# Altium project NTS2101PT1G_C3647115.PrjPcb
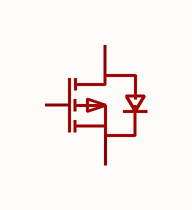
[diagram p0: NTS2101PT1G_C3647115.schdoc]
1 sheet, 1 parts. Net scope: global (net labels, ports and power ports of the same name join across sheets).

## Sheet NTS2101PT1G_C3647115.schdoc
size 127 x 101 mm

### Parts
Q?  nts2101pt1g-ms  [SOT-323-3_L2.2-W1.3-P1.30-LS2.1-BR]  (value not drawn)

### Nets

Not connected (* = marked no-connect by the designer): Q? 1(G) 2(S) 3(D)

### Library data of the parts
Q? = nts2101pt1g-ms: 数量:1个P沟道;漏源电压(Vdss):20V;连续漏极电流(Id):1.5A;导通电阻(RDS(on)):90mΩ@4.5V;耗散功率(Pd):312mW;阈值电压(Vgs(th)):600mV;; Manufacturer: MSKSEMI(美森科); Symbol: NTS2101PT1G_C3647115; AddInBom: yes; ModelId: 59529c0d6fc749f28f2d0659e12986b4; ModelName: SOT-323-3_L2.0-W1.3-H1.0-LS2.1-P1.30; ModelTransform: 78.74,82.677,0,90,0,0,-0.001,-0.001,0; Number: 1个P沟道; Drain to Source Voltage: 20V; Current - Continuous Drain(Id): 1.5A; Pd - Power Dissipation: 312mW; Gate Threshold Voltage (Vgs(th)): 600mV; Gate Charge(Qg): 4.8nC@4.5V; Input Capacitance(Ciss): 350pF; Reverse Transfer Capacitance (Crss@Vds): 50pF; Type: P沟道; Output Capacitance(Coss): 65pF; Vgs: ±12V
